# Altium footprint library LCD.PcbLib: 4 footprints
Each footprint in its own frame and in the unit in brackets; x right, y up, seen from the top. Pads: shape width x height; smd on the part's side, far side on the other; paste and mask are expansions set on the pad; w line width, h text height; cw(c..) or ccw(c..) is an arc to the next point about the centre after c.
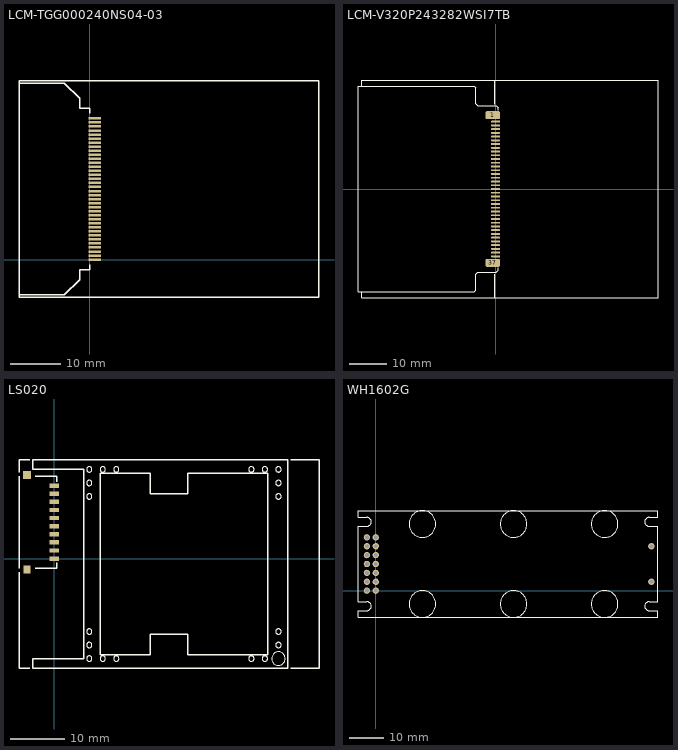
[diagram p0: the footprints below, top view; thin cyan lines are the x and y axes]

## LCM-TGG000240NS04-03 [mm]
pads (36):
  rect 2.5x0.5 smd: 1(1,0) 2(1,0.8) 3(1,1.6) 4(1,2.4) 5(1,3.2) 6(1,4) 7(1,4.8) 8(1,5.6) 9(1,6.4) 10(1,7.2) 11(1,8) 12(1,8.8) 13(1,9.6) 14(1,10.4) 15(1,11.2) 16(1,12) 17(1,12.8) 18(1,13.6) 19(1,14.4) 20(1,15.2) 21(1,16) 22(1,16.8) 23(1,17.6) 24(1,18.4) 25(1,19.2) 26(1,20) 27(1,20.8) 28(1,21.6) 29(1,22.4) 30(1,23.2) 31(1,24) 32(1,24.8) 33(1,25.6) 34(1,26.4) 35(1,27.2) 36(1,28)
Top Overlay:
  lines w0.254: -14,-7 -5,-7 -2,-4 -2,-2 0,-2 0,-1 ; -14,35 -5,35 -2,32 -2,30 0,30 0,29 ; -14,-7.5 -14,35.5 45.5,35.5 45.5,-7.5 -14,-7.5
3D body: height 3.4, standoff -0.1, extent -14,-7.5 45.5,35.5

## LCM-V320P243282WSI7TB [mm]
height 5
pads (39):
  rrect50% 4x2.15 smd: 1(-0.75,19.75) 37(-0.75,-19.75)
  oval 2.5x0.5 smd: 1(0,18) 2(0,17) 3(0,16) 4(0,15) 5(0,14) 6(0,13) 7(0,12) 8(0,11) 9(0,10) 10(0,9) 11(0,8) 12(0,7) 13(0,6) 14(0,5) 15(0,4) 16(0,3) 17(0,2) 18(0,1) 19(0,0) 20(0,-1) 21(0,-2) 22(0,-3) 23(0,-4) 24(0,-5) 25(0,-6) 26(0,-7) 27(0,-8) 28(0,-9) 29(0,-10) 30(0,-11) 31(0,-12) 32(0,-13) 33(0,-14) 34(0,-15) 35(0,-16) 36(0,-17) 37(0,-18)
Top Overlay:
  lines w0.254: -35.8,-27.5 -35.8,-29 -0.25,-29 ; -35.8,27.5 -35.8,29 -0.25,29 ; -0.25,-22.75 -0.25,-23.75 -0.25,-29 ; -0.25,22.625 -0.25,29 ; 0.75,-21 0.75,-21.75 0.25,-22.25 -4.75,-22.25 -5.25,-22.75 -5.25,-27 -5.75,-27.5 -36.75,-27.5 -36.75,27.5 -5.75,27.5 -5.25,27 -5.25,22.75 -4.75,22.25 0.25,22.25 0.75,21.75 0.75,21 ; -0.25,-29 36.75,-29 43.4,-29 43.4,22.35 43.4,29 -0.25,29
3D body: height 5.8, standoff 0.3, extent -37.25,-28.77 43.8,28.77

## LS020 [mm]
height 3.5
pads (12):
  rect 1.8x0.8 smd: 1(0,0) 2(0,1.5) 3(0,3) 4(0,4.5) 5(0,6) 6(0,7.5) 7(0,9) 8(0,10.5) 9(0,12) 10(0,13.5)
  rect 1.5x1.5 smd: 11(-5,15.5)
  rect 1.3x1.5 smd: 12(-5,-2)
Top Overlay:
  circle w0.2: c36.5,16.5 r0.5
  circle w0.2: c39,16.5 r0.5
  circle w0.2: c41.5,11.5 r0.5
  circle w0.2: c41.5,14 r0.5
  circle w0.2: c41.5,16.5 r0.5
  circle w0.2: c41.5,-13.5 r0.5
  circle w0.2: c41.5,-16 r0.5
  circle w0.2: c36.5,-18.5 r0.5
  circle w0.2: c39,-18.5 r0.5
  circle w0.2: c41.5,-18.5 r1.25
  circle w0.2: c6.5,-13.5 r0.5
  circle w0.2: c6.5,-16 r0.5
  circle w0.2: c11.5,-18.5 r0.5
  circle w0.2: c9,-18.5 r0.5
  circle w0.2: c6.5,-18.5 r0.5
  circle w0.2: c6.5,11.5 r0.5
  circle w0.2: c6.5,14 r0.5
  circle w0.2: c11.5,16.5 r0.5
  circle w0.2: c9,16.5 r0.5
  circle w0.2: c6.5,16.5 r0.5
  lines w0.254: -6.5,-2.5 -6.5,-20.25 -4.5,-20.25 ; -6.5,-1.75 -6.5,15.25 ; -6.5,16 -6.5,18.25 -4.5,18.25 ; -3.5,-1.75 0.5,-1.75 0.5,-0.75 ; -3.5,15.25 0.5,15.25 0.5,14.25 ; 43.75,-20.25 49,-20.25 49,18.25 43.75,18.25 ; -4,-20.25 43.25,-20.25 43.25,18.25 -4,18.25 -4,16.5 5.5,16.5 5.5,-18.5 -4,-18.5 -4,-20.25 ; 8.5,-17.75 17.75,-17.75 17.75,-14 24.75,-14 24.75,-17.75 39.5,-17.75 39.5,15.75 24.75,15.75 24.75,12 17.75,12 17.75,15.75 8.5,15.75 8.5,-17.75
3D body: height 3.61, standoff 0, extent -6.75,-20.5 49.25,18.5

## WH1602G [mm]
height 18
pads (16):
  round 1.8 hole 1.1: 1(0,0) 2(-2.54,0) 3(0,2.54) 4(-2.54,2.54) 5(0,5.08) 6(-2.54,5.08) 7(0,7.62) 8(-2.54,7.62) 9(0,10.16) 10(-2.54,10.16) 11(0,12.7) 12(-2.54,12.7) 13(0,15.24) 14(-2.54,15.24) 15(78.74,2.54) 16(78.74,12.7)
Top Overlay:
  circle w0.254: c13.335,19.05 r3.81
  circle w0.254: c13.335,-3.81 r3.81
  circle w0.254: c39.37,19.05 r3.81
  circle w0.254: c39.37,-3.81 r3.81
  circle w0.254: c65.405,19.05 r3.81
  circle w0.254: c65.405,-3.81 r3.81
  lines w0.254: -5.08,-7.62 80.645,-7.62 80.645,-5.715 78.105,-5.715 cw(c78.105,-4.445) 78.105,-3.175 80.645,-3.175 80.645,18.415 78.105,18.415 cw(c78.105,19.685) 78.105,20.955 80.645,20.955 80.645,22.86 -5.08,22.86 -5.08,20.955 -2.54,20.955 cw(c-2.54,19.685) -2.54,18.415 -5.08,18.415 -5.08,-3.175 -2.54,-3.175 cw(c-2.54,-4.445) -2.54,-5.715 -5.08,-5.715 -5.08,-7.62
3D body: height 13.2, standoff 0.2, extent -4.445,-7.38 80.555,22.62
